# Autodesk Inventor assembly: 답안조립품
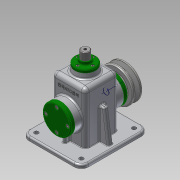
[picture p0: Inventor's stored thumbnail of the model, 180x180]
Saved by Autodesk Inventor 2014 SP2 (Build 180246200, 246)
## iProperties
Created: 2016-08
Part Number: 답안조립품
Document SubType Name: Assembly
Designer: user
Author: user
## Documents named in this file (19)
- C:\Users\user\Desktop\460820V1008\460820V1008(처음)\답안조립품.iam
- C:\Users\user\Desktop\460820V1008\460820V1008(처음)\본체.ipt
- C:\Users\user\Desktop\460820V1008\460820V1008(처음)\뒤커버.ipt
- C:\Users\user\Desktop\460820V1008\460820V1008(처음)\앞커버.ipt
- C:\Users\user\Desktop\460820V1008\460820V1008(처음)\볼트 M4 x 10.ipt
- C:\Users\user\Desktop\460820V1008\460820V1008(처음)\상부부시.ipt
- C:\Users\user\Desktop\460820V1008\460820V1008(처음)\볼트 M3 x 8.ipt
- C:\Users\user\Desktop\460820V1008\460820V1008(처음)\오일실 15 25 7.ipt
- C:\Users\user\Desktop\460820V1008\460820V1008(처음)\베어링 15 x 35 x 11.ipt
- C:\Users\user\Desktop\460820V1008\460820V1008(처음)\편심축.ipt
- C:\Users\user\Desktop\460820V1008\460820V1008(처음)\키 5 x 5 x 14.ipt
- C:\Users\user\Desktop\460820V1008\460820V1008(처음)\슬라이드바.ipt
- C:\Users\user\Desktop\460820V1008\460820V1008(처음)\멈춤링 15 x 1.ipt
- C:\Users\user\Desktop\460820V1008\460820V1008(처음)\V-벨트풀리.ipt
- C:\Users\user\Desktop\460820V1008\460820V1008(처음)\링크.ipt
- C:\Users\user\Desktop\460820V1008\460820V1008(처음)\고정핀.ipt
- C:\Users\user\Desktop\460820V1008\460820V1008(처음)\와셔.ipt
- C:\Users\user\Desktop\460820V1008\460820V1008(처음)\볼트 M6 x 12.ipt
- C:\Users\user\Desktop\460820V1008\460820V1008(처음)\멈춤링 6 x 5.ipt
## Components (15 placed, 5 different names)
1. V-벨트풀리:1 — 각도:1
2. 고정핀:1 — 각도:2
3. ISO 4018 M6 x 12:1 — 강체:4
4. ISO 4762 M4 x 10:1 — 강체:1
5. ISO 4762 M4 x 10:3
6. ISO 4762 M4 x 10:4
7. ISO 4762 M4 x 10:5
8. ISO 4762 M4 x 10:2 — 강체:2
9. ISO 4762 M4 x 10:6
10. ISO 4762 M4 x 10:7
11. ISO 4762 M4 x 10:8
12. ISO 4762 M3 x 8:1 — 강체:3
13. ISO 4762 M3 x 8:2
14. ISO 4762 M3 x 8:3
15. ISO 4762 M3 x 8:4
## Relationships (6: WeldJoint 4, Angle 2)
- 강체:1 [WeldJoint]: ISO 4762 M4 x 10:1
- 강체:2 [WeldJoint]: ISO 4762 M4 x 10:2
- 강체:3 [WeldJoint]: ISO 4762 M3 x 8:1
- 각도:1 [Angle]: V-벨트풀리:1
- 강체:4 [WeldJoint]: ISO 4018 M6 x 12:1
- 각도:2 [Angle]: 고정핀:1
